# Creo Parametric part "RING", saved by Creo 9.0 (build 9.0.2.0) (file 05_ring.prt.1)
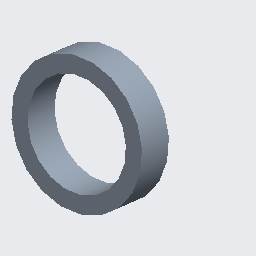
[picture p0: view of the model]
Units: millimeter Newton Second (mmNs); MM, TONNE, SECS

Created from: XX_MMNS_PART_SOLID_ABS.PRT

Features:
  1. datum plane "RIGHT"
  2. datum plane "TOP"
  3. datum plane "FRONT"
  4. coordinate system
  5. extrusion "Extrude 1"

Surfaces: 2 plane, 2 cylinder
